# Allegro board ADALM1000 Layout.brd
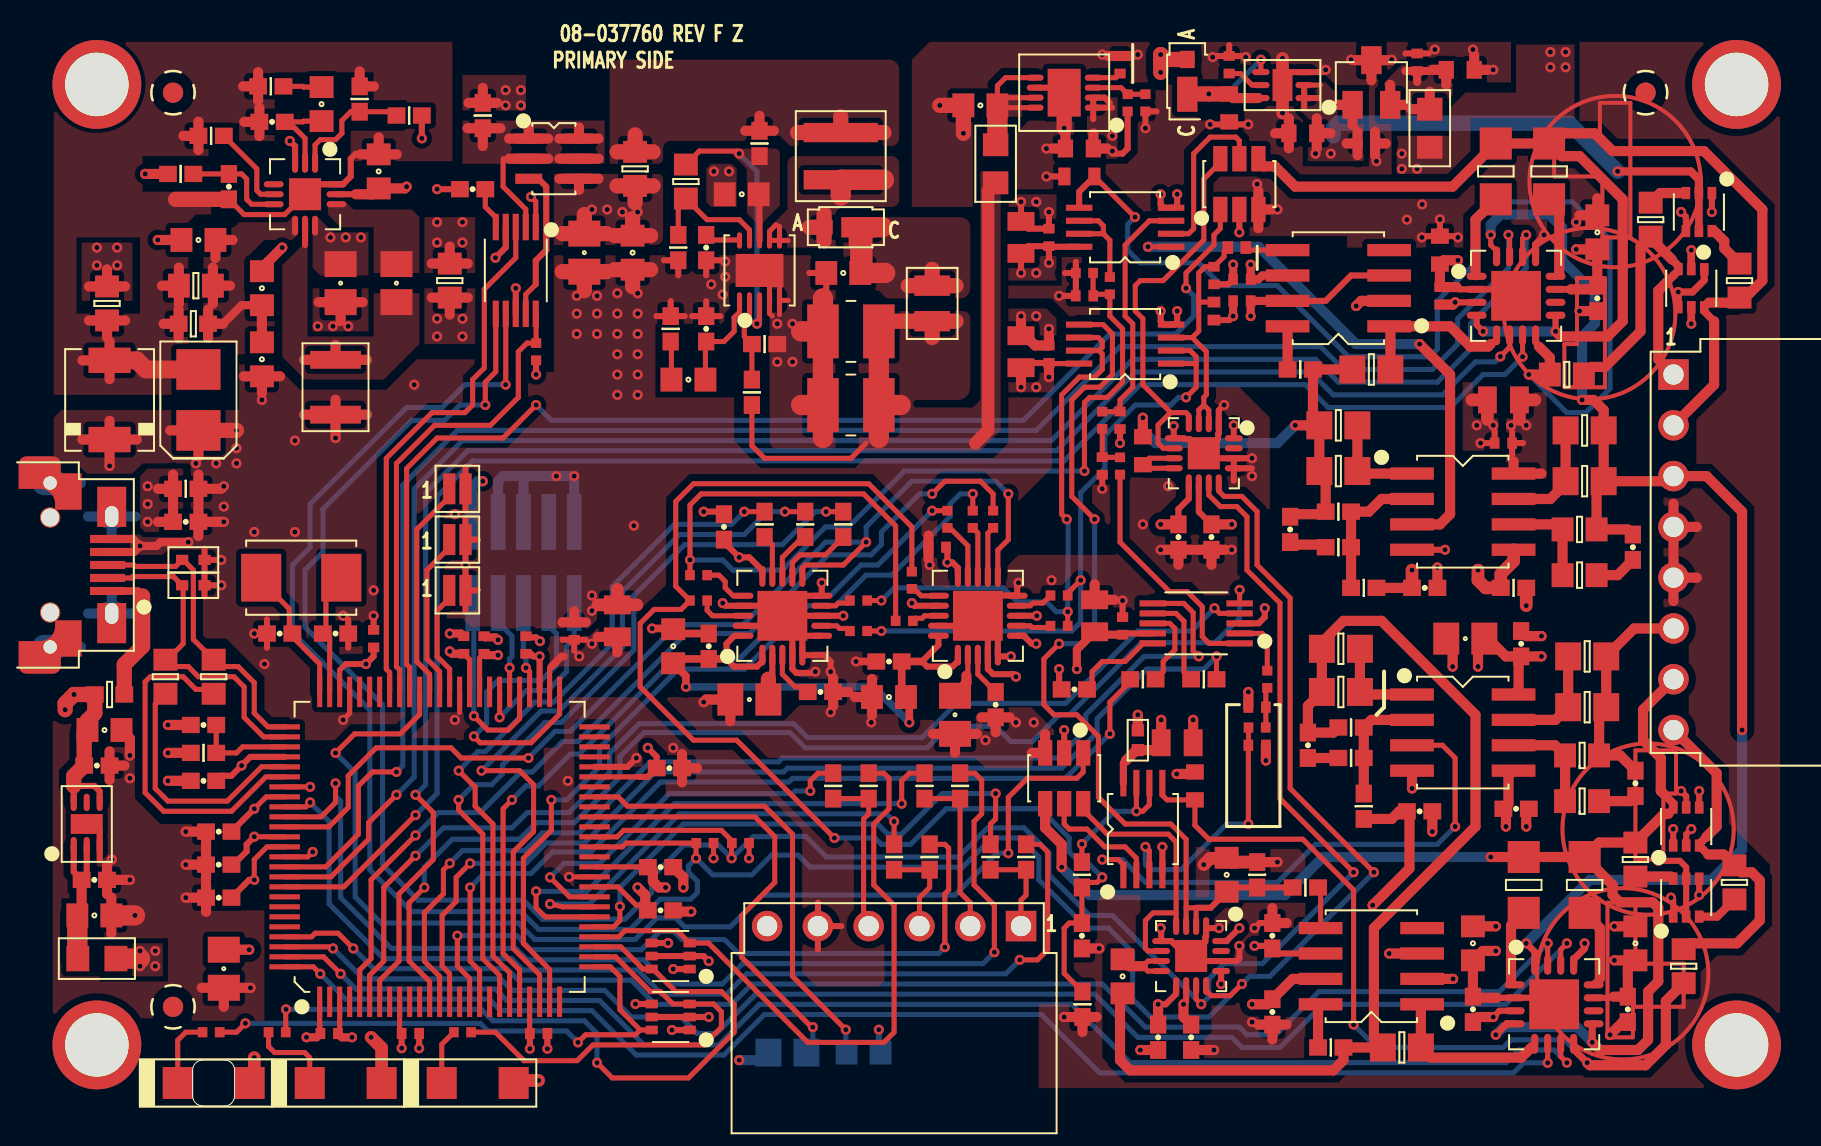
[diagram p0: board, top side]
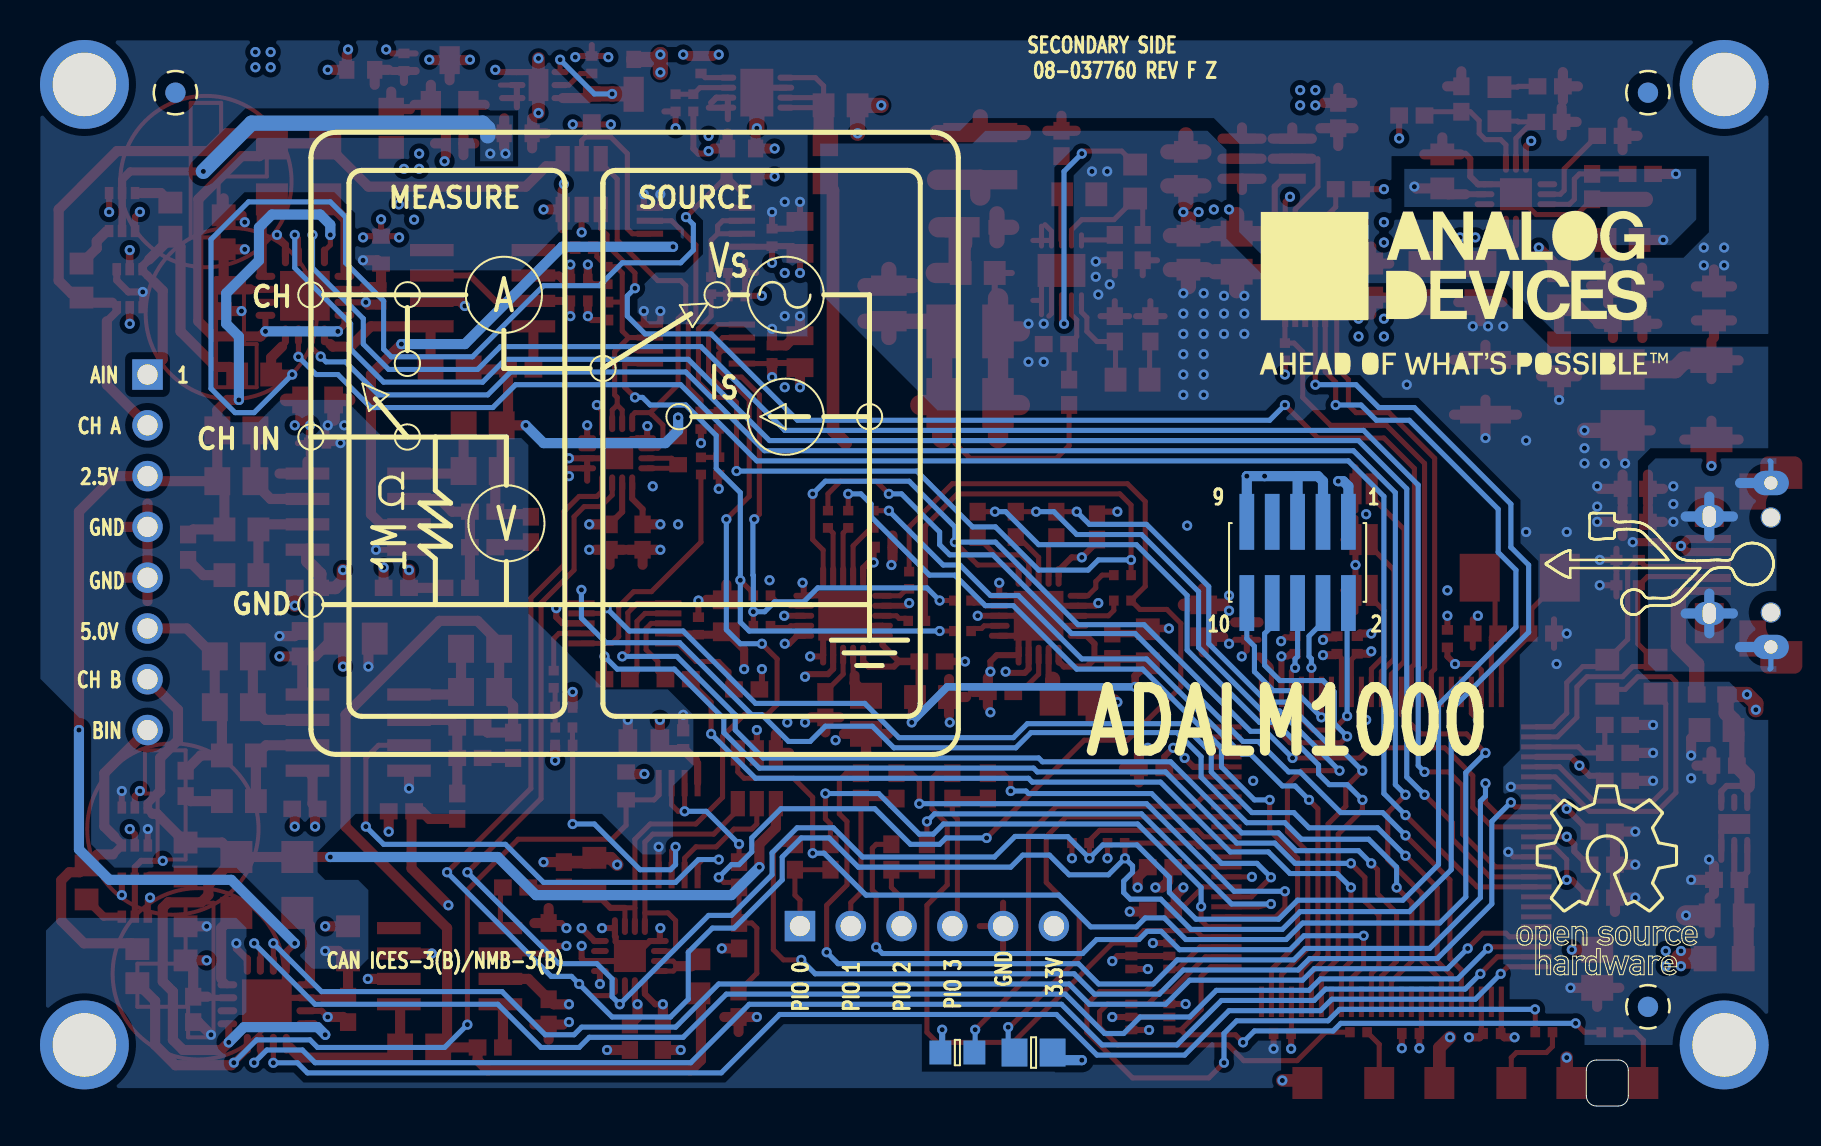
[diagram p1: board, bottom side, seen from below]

Outline 2.1 x 2.3 mm; copper layers: TOP, L2_GND, L3_VDD, BOTTOM. Coordinates in mm from the lower left corner of the outline.
Outline path: 0,1.79 0,0.51 arc(0.15,0.15) 0.51,0 1.59,0 arc(1.95,0.15) 2.1,0.51 2.1,1.79 arc(1.95,2.15) 1.59,2.3 0.51,2.3 arc(0.15,2.15) 0,1.79

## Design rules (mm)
constraint set DEFAULT: min track width 0.254
net group USB: nets D+ D-
net group USB_A: nets D+_A D-_A
nets with their own width: min track width 0.305; nets 1V8 2V5 3V3 5V0 6V0 -1V0 GND VCC

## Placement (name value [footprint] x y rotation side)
A2  ADG719BRTZ  [SOT23_6]  52.36 46.11 0 top
A3  ADA4661-2ARMZ  [MSOP8]  46.64 43.95 90 top
A4  AD8018ARZ  [SO8]  63.53 29.73 270 top
B2  ADG719BRTZ  [SOT23_6]  43.6 16.39 180 top
B3  ADA4661-2ARMZ  [MSOP8]  47.53 13.85 0 top
B4  AD8018ARZ  [SO8]  63.53 18.68 270 top
C1  10uF  [C0805]  1.56 6.87 270 top
C2  0.1UF  [C0402#2]  6.83 3.63 180 top
C3  10uF  [C0805#2]  21.24 24.26 90 top
C4  0.1UF  [C0402#2]  10.89 3.63 180 top
C5  10pF  [C0402]  0.54 19.06 0 top
C6  12PF  [C0402]  7.15 23.63 0 top
C7  12PF  [C0402]  4.35 23.63 180 top
C8  0.1UF  [C0402#2]  61.25 52.2 270 top
C9  0.1UF  [C0402]  -4.79 17.03 180 top
C10  1UF  [C0603#2]  63.41 51.82 0 top
C11  0.1UF  [C0402]  14 45.85 0 top
C12  4.7uF  [C0603]  -4.41 18.8 0 top
C13  0.1UF  [C0402#2]  58.71 48.14 180 top
C14  0.1UF  [C0402]  -4.92 11.31 180 top
C15  4.7uF  [C0603]  -4.92 9.53 0 top
C17  1UF  [C0603]  22.01 42.68 270 top
C18  10uF  [C0805]  19.59 42.68 90 top
C19  0.1UF  [C0402#2]  17.31 3.63 180 top
C20  10pF  [C0402]  25.69 38.87 90 top
C21  0.1UF  [C0402#2]  37.25 27.95 0 top
C22  1UF  [C0603]  34.83 20.45 180 top
C23  1UF  [C0603]  27.47 45.6 180 top
C24  0.1UF  [C0402]  23.4 9.79 180 top
C25  0.1UF  [C0402]  34.83 22.23 0 top
C26  0.01uF  [C0402]  44.48 8.52 90 top
C27  0.0056uF  [C0603#3]  51.09 41.54 270 top
C28  0.0056uF  [C0603]  51.72 11.56 90 top
C29  47uF  [C1210-2]  32.93 35.06 180 top
C30  1UF  [C0603]  32.55 41.66 180 top
C31  0.01uF  [C0402]  66.2 14.87 0 top
C32  0.1UF  [C0402]  23.4 11.95 180 top
C33  0.1UF  [C0402#2]  19.08 23.76 270 top
C34  0.1UF  [C0402]  23.85 16.9 180 top
C35  0.1UF  [C0402#2]  14.58 23.06 270 top
C36  0.1UF  [C0402#2]  16.67 23.06 270 top
C37  0.1UF  [C0402#2]  9.05 23.38 270 top
C38  0.1UF  [C0402]  26.58 28.96 270 top
C39  0.001uF  [C0603]  46.52 6.48 270 top
C40  0.1UF  [C0402]  61.38 14.74 180 top
C41  0.1UF  [C0402#2]  42.83 37.6 270 top
C42  0.01uF  [C0402#2]  44.61 40.52 0 top
C43  0.001uF  [C0603#2]  47.53 32.77 90 top
C44  0.1UF  [C0402]  61.63 25.92 180 top
C45  47uF  [C1210-2]  32.93 38.74 180 top
C46  0.1UF  [C0402]  70.27 40.39 90 top
C47  10uF  [C0805#2]  41.44 37.73 90 top
C48  0.1UF  [C0402#2]  13.56 23.06 270 top
C49  0.1UF  [C0402#2]  52.49 40.27 0 top
C50  0.1UF  [C0402]  1.3 13.72 0 top
C51  0.1UF  [C0402]  0.54 16.26 0 top
C52  0.1UF  [C0402]  1.3 12.07 0 top
C53  0.1UF  [C0402]  1.3 10.42 0 top
C54  0.1UF  [C0402#2]  42.83 43.44 270 top
C55  0.1UF  [C0402]  48.29 3.44 270 top
C56  0.1UF  [C0402]  49.95 3.44 90 top
C57  10pF  [C0402]  72.17 16.14 90 top
C58  0.1UF  [C0402]  71.79 4.83 90 top
C59  1UF  [C0603]  24.04 22.99 90 top
C61  0.1UF  [C0402]  25.82 22.99 270 top
C62  1UF  [C0603]  72.17 8.14 90 top
C63  0.1UF  [C0402#2]  46.52 24.01 270 top
C64  10uF  [C0805#2]  45.12 24.52 270 top
C65  0.1UF  [C0402]  49.31 28.46 270 top
C66  0.1UF  [C0402]  50.96 28.46 90 top
C67  33pF  [C0402]  54.9 28.84 90 top
C68  1UF  [C0603]  70.27 43.7 90 top
C69  0.1UF  [C0402#2]  52.49 41.35 180 top
C70  0.1UF  [C0402]  54.01 8.52 90 top
C71  0.1UF  [C0402]  54.01 4.71 90 top
C72  10uF  [C0805]  27.85 20.33 0 top
C73  10uF  [C0805]  38.13 19.57 90 top
C74  0.1UF  [C0402]  31.4 20.71 180 top
C75  0.1UF  [C0402]  40.17 20.07 90 top
C76  10uF  [C0805#2]  41.44 43.44 90 top
C77  0.1UF  [C0402#2]  65.57 33.15 0 top
C78  10uF  [C0805#2]  65.57 35.31 180 top
C79  0.1UF  [C0402#3]  47.28 18.3 270 top
C80  10uF  [C0805#2]  49.25 18.17 0 top
C81  0.1UF  [C0402]  66.46 23.12 270 top
C82  10uF  [C0805]  63.66 23.38 180 top
C84  33pF  [C0402]  55.79 18.04 90 top
C90  0.1UF  [C0402#2]  62.39 40.52 90 top
C91  1UF  [C0603#2]  62.39 42.81 90 top
C92  0.1UF  [C0402]  64.04 4.83 90 top
C93  1UF  [C0603]  64.04 8.14 90 top
C94  0.01uF  [C0402#2]  45.5 32.01 90 top
C95  0.01uF  [C0402#2]  53.25 19.95 0 top
C96  1000PF  [C0402#2]  46.39 34.3 270 top
C97  1000PF  [C0402#2]  53.25 18.04 0 top
C99  0.1UF  [C0402]  44.1 20.84 0 top
C101  10pF  [C0402]  -0.35 29.22 180 top
C102  10pF  [C0402]  72.04 27.95 90 top
C104  4.7uF  [C0603]  39.4 50.05 180 top
C105  0.01uF  [C0402#2]  46.39 52.08 270 top
C106  4.7uF  [C0603#2]  44.36 47.89 180 top
C107  2.2uF  [C0603#2]  51.85 49.92 270 top
C108  2.2uF  [C0603#2]  55.53 48.65 180 top
C109  0.01uF  [C0402]  25.69 42.93 90 top
C110  0.082UF  [C0603]  24.8 36.33 0 top
C112  0.01uF  [C0402#2]  51.85 52.08 270 top
CBST  0.01uF  [C0805]  10.19 41.16 270 top
CC  1UF  [C0603]  3.46 40.9 90 top
CC1  2700PF  [C0603]  6.45 50.11 270 top
CC2  22PF  [C0402]  3.97 49.22 0 top
CIN1  10uF  [C0805]  7.4 41.16 270 top
COUT1  4.7uF  [C0603]  3.46 37.35 90 top
COUT2  47UF  [C3528]  0.29 35.31 90 top
CSS  TBD0402  [C0402]  1.81 45.98 90 top
CVCC  1UF  [C0603]  9.31 46.74 90 top
CVCC2  1UF  [C0603]  0.29 43.31 0 top
D1  B160B-13-F  [DIO214AA]  -4.16 35.31 90 top
D2  BAT54SDW-7-F  [SOT363H43]  75.35 44.71 180 top
D3  PD3S130L-7  [POWERDI323]  49.75 51.25 90 top
D4  PD3S130L-7  [POWERDI323]  32.67 43.95 180 top
D5  BAT54SDW-7-F  [SOT363H43]  23.91 4.45 90 top
D6  BAT54SDW-7-F  [SOT363H43]  23.91 7.5 90 top
D7  BAT54SDW-7-F  [SOT363H43]  74.96 40.9 180 top
D8  MLESD12A-0402-TP  [D0402]  0.03 26.04 180 top
D9  MLESD12A-0402-TP  [D0402]  0.03 27.31 180 top
D10  BAT54SDW-7-F  [SOT363H43]  74.71 13.98 0 top
D11  BAT54SDW-7-F  [SOT363H43]  74.71 10.42 0 top
DS1  LTST-C230KRKT  [LED1206H11]  1.05 1.15 0 top
DS2  LTST-C230KGKT  [LED1206H11]  7.65 1.15 0 top
DS3  LTST-C230TBKT  [LED1206H11]  14.26 1.15 0 top
E1  330OHM  [L0603]  -4.16 20.58 0 top
E2  100OHM  [L0805]  61.88 48.9 270 top
E3  100OHM  [L0805]  -4.79 7.37 0 top
E4  100OHM  [L0805]  40.17 47.12 90 top
JTAG  FTSH-105-01-L-DV-TR  [CNHDR2X5H245]  16.54 27.19 0 bottom
L1  2.2uH  [LSML126W90H59]  7.15 35.95 270 top
L2  1uH  [L0603]  0.03 39.12 0 top
L3  4.7uH  [LSMSQ157H122]  32.42 47.51 270 top
L4  110nH  [L9075]  36.99 40.14 270 top
NOREF  -  []  -6.12 35.06 0 top
NOREF#2  -  [unnamed#2]  -0.98 4.96 0 top
NOREF#3  -  []  14.19 0.26 0 top
NOREF#4  -  []  1.1 0.35 0 top
NOREF#5  -  []  7.72 0.35 0 top
NOREF#6  -  [unnamed#2]  77.23 3.06 0 top
NOREF#7  -  []  -148.3 -209.03 0 top
NOREF#8  -  []  -148.3 -209.03 0 top
NOREF#9  -  []  -8.78 29.78 0 top
NOREF#10  -  []  -101.54 140.49 0 top
NOREF#11  -  []  -6.57 24.52 0 top
NOREF#12  -  [unnamed#2]  -0.98 50.68 0 top
NOREF#13  -  []  111.16 107.32 0 top
NOREF#14  -  []  -142.97 -60.74 0 top
NOREF#15  -  []  166.02 61.48 0 top
NOREF#16  -  [unnamed#2]  -7.13 29.43 0 top
NOREF#17  -  [unnamed#2]  77.23 51.09 0 top
NOREF#18  -  [unnamed#2]  -4.79 3.06 0 top
NOREF#19  -  []  37.76 69.2 0 top
NOREF#20  -  []  -148.3 -209.03 0 top
NOREF#21  -  [unnamed#2]  -7.13 24.68 0 top
NOREF#22  -  []  14.8 0.51 0 top
NOREF#23  -  [unnamed#2]  72.68 50.68 0 top
NOREF#24  -  [unnamed#2]  -4.79 51.09 0 top
NOREF#25  -  []  8.8 40.65 180 bottom
NOREF#26  -  [unnamed#2]  -0.98 50.68 180 bottom
NOREF#27  -  [unnamed#2]  72.68 50.68 180 bottom
NOREF#28  -  [unnamed#2]  -0.98 4.96 180 bottom
P1  10103592-0001LF  [CNFCI10103592-0001LF]  -6.96 27.06 90 top
P2  PPPC081LGBN-RC  [CNHDRRA1X8H108]  74.08 36.58 270 top
P3  PPPC061LGBN-RC  [CNHDRRA1X6H108]  41.44 9 180 top
P4  -  [JPSLD02]  13.24 25.79 0 top
P5  -  [JPSLD02]  13.24 28.33 0 top
P6  -  [JPSLD02]  13.24 30.87 0 top
Q1  SI3456DDV-T1-GE3  [TSOP6]  18.07 47.38 270 top
R1  10K  [R0402]  25.62 13.15 180 top
R2  10K  [R0402]  27.4 13.15 180 top
R3  6.8K  [R0402#2]  0.54 17.66 0 top
R4  39  [R0603]  1.05 21.47 90 top
R5  39  [R0603]  -1.36 21.47 90 top
R6  0.1  [R0402#2]  14.51 49.54 270 top
R7  150  [R0402#2]  44.48 11.56 90 top
R8  1MEG  [R0603#2]  50.14 16.01 90 top
R9  10K  [R0402#2]  58.58 14.99 90 top
R10  10K  [R0402#2]  57.95 18.93 180 top
R11  0  [R0603]  24.67 46.24 90 top
R12  62K  [R0402#2]  24.29 42.93 270 top
R13  0  [R0805]  29.75 2.67 0 bottom
R14  4.7K  [R0402#2]  39.91 12.45 270 top
R15  255  [R0402#3]  52.23 42.93 180 top
R16  255  [R0402#2]  55.66 10.93 180 top
R17  1K  [R0402#2]  66.07 25.92 0 top
R18  53.6K  [R0402#2]  27.97 35.69 90 top
R19  12.7K  [R0402#2]  28.61 38.11 180 top
R20  150  [R0402]  45.88 41.03 90 top
R21  0  [R0402#2]  -0.6 46.62 180 top
R22  1.02K  [R0402#3]  51.09 39.76 270 top
R23  4.7K  [R0402#2]  36.61 16.01 270 top
R24  10K  [R0402#2]  58.58 25.92 180 top
R25  10K  [R0402#2]  57.31 29.73 180 top
R26  100  [R0402#2]  57.31 27.95 180 top
R27  604  [R0402#2]  44.51 5.09 270 top
R28  49.9  [R1206]  67.85 46.74 90 top
R29  100  [R0603]  68.74 36.58 0 top
R30  0.5  [R0805]  58.96 36.84 0 top
R31  100  [R0603]  74.58 6.99 90 top
R32  0.5  [R0805]  60.49 2.93 0 top
R33  2.49K  [R0603]  69.5 17.53 0 top
R34  100  [R0402#2]  57.95 17.41 180 top
R35  4.7K  [R0402#2]  35.09 12.45 270 top
R36  0  [R0603]  -4.28 40.14 270 top
R37  0  [R0603]  12.86 41.28 270 top
R38  1MEG  [R0603#3]  44.36 46.49 180 top
R39  2.49K  [R0603]  69.38 28.84 0 top
R40  1.02K  [R0402#2]  53.25 11.56 90 top
R41  130  [R0402]  0.92 3.69 0 top
R42  130  [R0402]  13.5 3.69 0 top
R43  130  [R0402]  4.23 3.69 0 top
R44  4.7K  [R0402#2]  32.04 16.01 270 top
R45  1  [R0402#2]  28.36 48.14 90 top
R46  8.06  [R0805]  57.31 31.76 180 top
R47  8.06  [R0805]  57.31 34.04 180 top
R48  49.9  [R1206]  65.19 46.74 90 top
R49  8.06  [R0805]  69.63 33.79 0 top
R50  220  [R0402#2]  41.69 12.45 90 top
R51  220  [R0402#2]  36.86 12.45 90 top
R52  220  [R0402#2]  38.39 16.01 90 top
R53  220  [R0402#2]  33.82 16.01 90 top
R54  0  [R0603]  22.13 46.87 90 top
R55  100K  [R0402#2]  -0.35 30.87 180 top
R56  0  [R0603]  33.56 2.67 180 bottom
R57  8.06  [R0805]  69.63 31.25 0 top
R58  100  [R0603]  69.5 15.25 0 top
R59  8.06  [R0805]  57.44 22.87 180 top
R60  100  [R0603]  69.38 26.55 0 top
R61  8.06  [R0805]  57.44 20.71 180 top
R62  604  [R0402]  44.61 41.66 180 top
R63  49.9  [R1206]  69.63 11.06 90 top
R64  49.9  [R1206]  66.58 11.06 90 top
R65  8.06  [R0805]  69.76 19.95 0 top
R66  8.06  [R0805]  69.76 22.49 0 top
R67  10  [R0603]  72.17 12.33 270 top
R68  10  [R0603]  77.12 11.18 270 top
R69  10  [R0402]  25.31 26.55 0 top
R70  10  [R0603]  77.38 41.28 90 top
R71  10  [R0603]  72.93 44.33 90 top
R72  33  [R0402#2]  50.58 21.34 180 top
R73  33  [R0402#2]  47.53 21.34 0 top
R74  150  [R0402]  46.39 32.01 90 top
R75  150  [R0402]  53.76 21.34 270 top
R76  1.5K  [R0402]  45.5 34.3 90 top
R77  1.5K  [R0402]  53.25 18.93 180 top
R78  33  [R0402#2]  32.55 29.09 270 top
R79  33  [R0402#2]  30.64 29.09 270 top
R80  33  [R0402#2]  28.61 29.09 90 top
R81  33  [R0402]  40.04 29.34 270 top
R82  33  [R0402]  39.02 29.34 270 top
R83  33  [R0402]  37.75 29.34 90 top
R84  0.5  [R0402#2]  55.41 36.84 180 top
R85  0.5  [R0402#2]  56.93 2.93 180 top
R86  10  [R0402]  33.31 23.76 180 top
R87  10  [R0402]  35.98 26.3 270 top
R88  10  [R0402]  43.34 24.01 180 top
R89  10  [R0402]  25.31 25.28 0 top
R90  10  [R0402]  33.31 25.28 180 top
R91  10  [R0402]  35.59 24.26 0 top
R92  10  [R0402]  43.34 25.53 180 top
R93  10K  [R0402]  17.18 37.73 90 top
R95  10.5K  [R0402#2]  23.91 38.87 270 top
R97  20K  [R0402]  46.77 50.17 90 top
R98  4.99K  [R0402]  47.66 50.17 270 top
RC1  11.3K  [R0402#2]  3.91 51 0 top
RF1  23.2K  [R0402#2]  10.83 49.54 0 top
RF2  34.8K  [R0402#2]  8.35 50.36 270 top
RFILT  1  [R0603]  0.16 41.03 0 top
RFREQ  88.7K  [R0402#2]  0.92 48.52 0 top
U1  ATSAM3U2CA-AU  [LQFP100]  12.35 12.96 0 top
U2  ADM1178-1ARMZ  [RM10]  16.16 41.79 180 top
U3  ADP7118ACPZN3.3  [DFN6_2X2_PAD1_6X1]  -5.3 14.1 0 top
U4  ADR381ARTZ  [SOT23]  58.96 51.19 0 top
U5  ADP2442ACPZ  [QFN12_3X3_PAD1_6X1_6]  5.62 45.6 180 top
U6  ADM7171ACPZ  [DFN8_3X3_PAD2_38X1_64]  43.6 50.68 90 top
U7  ADP7118ACPZN5.0  [DFN6_2X2_PAD1_6X1]  54.52 51.06 90 top
U8  ADA4661-2ARMZ  [MSOP8]  46.64 38.11 90 top
U9  ADP1614ACPZ-1.3  [QFN10_3X3_PAD2_38X1_64]  28.36 41.79 0 top
U10  AD5663RBRMZ-5  [RM10]  50.2 24.14 90 top
U11  AD7682BCPZ  [QFN20_4X4_PAD2_5X2_5]  29.5 24.52 0 top
U12  AD7682BCPZ  [QFN20_4X4_PAD2_5X2_5]  39.28 24.52 0 top
UA9  AD5122ABCPZ10  [QFN16_3X3_PAD1_6X1_6]  50.58 32.65 180 top
UA11  ADG1611BCPZ  [QFN16_4X4_PAD2_5X2_5]  66.2 40.52 270 top
UA12  AD8210WYRZ  [SO8]  57.31 40.9 90 top
UB9  AD5122ABCPZ10  [QFN16_3X3_PAD1_6X1_6]  49.95 7.5 180 top
UB11  ADG1611BCPZ  [QFN16_4X4_PAD2_5X2_5]  68.11 5.09 270 top
UB12  AD8210WYRZ  [SO8]  58.96 6.99 90 top
Y1  12MEGHZ  [YSML197W126H59]  5.43 26.42 180 top

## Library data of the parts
A2 B2 = ADG719BRT: User Part Number: UPN; Tolerance: N/A; alternate symbols: (); part number: ADG719BRT_SM-ADG719BRTZ,E005069,SOT23_6; tolerance: N/A
A3 B3 U8 = ADA4661_2_V2: Tolerance: N/A; User Part Number: UPN; alternate symbols: (); part number: ADA4661_2_V2_SM-ADA4661-2ARMZ,E019683,MSOP8; tolerance: N/A
A4 B4 = AD8018: Tolerance: N/A; User Part Number: UPN; alternate symbols: (); part number: AD8018_SM-AD8018ARZ,E020278,SO8; tolerance: N/A
C1 C18 C72 C73 C82 CIN1 = CAP: Tolerance: 10; User Part Number: UPN; alternate symbols: (); part number: CAP_SM-10UF,25V,10,E019080,C0805; tolerance: 10
C2 C4 C8 C13 C19 C21 C33 C35-C37 C41 C48 C49 C54 C61 C63 C69 C77 C90 C99 = CAP: Tolerance: 10; User Part Number: UPN; alternate symbols: C0402L_ALT; part number: CAP_SM-0.1UF,16V,10,E027519,C0402; tolerance: 10
C3 C47 C64 C76 C78 C80 = CAP: User Part Number: UPN; Tolerance: 10; alternate symbols: C0805L; part number: CAP_SM-10UF,25V,10,E019080,C0805; tolerance: 10
C5 C20 C57 C101 C102 = CAP: Tolerance: 5; User Part Number: UPN; alternate symbols: (); part number: CAP_SM-10PF,50V,5,E007982,C0402; tolerance: 5
C6 C7 = CAP: Tolerance: 5; User Part Number: UPN; alternate symbols: (); part number: CAP_SM-12PF,50V,5,E033360,C0402; tolerance: 5
C9 C11 C14 C24 C25 C32 C34 C38 C40 C44 C46 C50-C53 C55 C56 C58 C65 C66 C70 C71 C74 C75 C81 C92 = CAP: Tolerance: 10; User Part Number: UPN; alternate symbols: (); part number: CAP_SM-0.1UF,16V,10,E027519,C0402; tolerance: 10
C10 C59 C91 = CAP: Tolerance: 10; User Part Number: UPN; alternate symbols: C0603L_ALT; part number: CAP_SM-1UF,25V,10,E026591,C0603; tolerance: 10
C12 C15 COUT1 = CAP: Tolerance: 10; User Part Number: UPN; alternate symbols: (); part number: CAP_SM-4.7UF,6.3V,10,E010382,C0603; tolerance: 10
C17 C22 C23 C30 C62 C68 C93 CC CVCC CVCC2 = CAP: Tolerance: 10; User Part Number: UPN; alternate symbols: (); part number: CAP_SM-1UF,25V,10,E026591,C0603; tolerance: 10
C26 = CAP: Tolerance: 10; User Part Number: UPN; alternate symbols: (); part number: CAP_SM-0.01UF,50V,10,E019413,C0402; tolerance: 10
C27 = CAP: Tolerance: 5; User Part Number: UPN; alternate symbols: C0402L_ALT; part number: CAP_SM-0.0056UF,50V,5,E012693,C0603; tolerance: 5
C28 = CAP: Tolerance: 5; User Part Number: UPN; alternate symbols: (); part number: CAP_SM-0.0056UF,50V,5,E012693,C0603; tolerance: 5
C29 C45 = CAP: Tolerance: 10; User Part Number: UPN; alternate symbols: (); part number: CAP_SM-47UF,10V,10,E011546,C1210-2; tolerance: 10
C31 C109 = CAP: Tolerance: 10; User Part Number: UPN; alternate symbols: (); part number: CAP_SM-0.01UF,25V,10,E019646,C0402; tolerance: 10
C39 = CAP: Tolerance: 5; User Part Number: UPN; alternate symbols: (); part number: CAP_SM-0.001UF,50V,5,E007908,C0603; tolerance: 5
C42 C94 C95 = CAP: Tolerance: 10; User Part Number: UPN; alternate symbols: C0402L_ALT; part number: CAP_SM-0.01UF,50V,10,E019413,C0402; tolerance: 10
C43 = CAP: Tolerance: 5; User Part Number: UPN; alternate symbols: C0603L_ALT; part number: CAP_SM-0.001UF,50V,5,E007908,C0603; tolerance: 5
C67 C84 = CAP: Tolerance: 5; User Part Number: UPN; alternate symbols: (); part number: CAP_SM-33PF,50V,5,E007907,C0402; tolerance: 5
C79 = CAP: Tolerance: 10; User Part Number: UPN; alternate symbols: C0402_ALT; part number: CAP_SM-0.1UF,16V,10,E027519,C0402; tolerance: 10
C96 C97 = CAP: Tolerance: 10; User Part Number: UPN; alternate symbols: C0402L_ALT; part number: CAP_SM-1000PF,25V,10,E025706,C0402; tolerance: 10
C104 C106 = CAP: Tolerance: 10; User Part Number: UPN; alternate symbols: C0603L_ALT; part number: CAP_SM-4.7UF,16V,10,E020112,C0603; tolerance: 10
C105 C112 = CAP: Tolerance: 10; User Part Number: UPN; alternate symbols: C0402L_ALT; part number: CAP_SM-0.01UF,25V,10,E019646,C0402; tolerance: 10
C107 C108 = CAP: Tolerance: 10; User Part Number: UPN; alternate symbols: C0603L_ALT; part number: CAP_SM-2.2UF,10V,10,E015288,C0603; tolerance: 10
C110 = CAP: Tolerance: 10; User Part Number: UPN; alternate symbols: (); part number: CAP_SM-0.082UF,16V,10,E000419,C0603; tolerance: 10
CBST = CAP: Tolerance: 5; User Part Number: UPN; alternate symbols: (); part number: CAP_SM-0.01UF,50V,5,E012401,C0805; tolerance: 5
CC1 = CAP: Tolerance: 5; User Part Number: UPN; alternate symbols: (); part number: CAP_SM-2700PF,50V,5,E026401,C0603; tolerance: 5
CC2 = CAP: Tolerance: 5; User Part Number: UPN; alternate symbols: (); part number: CAP_SM-22PF,50V,5,E000265,C0402; tolerance: 5
COUT2 = CAPP: User Part Number: UPN; Tolerance: 10; alternate symbols: (); part number: CAPP_SM-47UF,10V,10,E014885,C3528; tolerance: 10
CSS = CAP: User Part Number: UPN; alternate symbols: (); part number: CAP_SM-TBD0402,TBD0402,TBD0402,E000381,C0402
D1 = DIOSCHOTTKY: User Part Number: UPN; Tolerance: N/A; alternate symbols: (); part number: DIOSCHOTTKY_SM-B160B-13-F,60V,N/A,E006709,DIO214AA; tolerance: N/A
D2 D5-D7 D10 D11 = DIO6P_V2: User Part Number: UPN; Tolerance: N/A; alternate symbols: (); part number: DIO6P_V2_SM-BAT54SDW-7-F,30V,N/A,E016644,SOT363H43; tolerance: N/A
D3 D4 = DIOSCHOTTKY: Tolerance: N/A; User Part Number: UPN; alternate symbols: (); part number: DIOSCHOTTKY_SM-PD3S130L-7,30V,N/A,E021289,POWERDI323; tolerance: N/A
D8 D9 = DIOZNR_V2: Tolerance: N/A; User Part Number: UPN; alternate symbols: (); part number: DIOZNR_V2_SM-MLESD12A-0402-TP,12V,N/A,E023287,D0402; tolerance: N/A
DS1 = DIOLED: User Part Number: UPN; Tolerance: N/A; alternate symbols: (); part number: DIOLED_SM-LTST-C230KRKT,2V,N/A,E027097,LED1206H11; tolerance: N/A
DS2 = DIOLED: User Part Number: UPN; Tolerance: N/A; alternate symbols: (); part number: DIOLED_SM-LTST-C230KGKT,2V,N/A,E027102,LED1206H11; tolerance: N/A
DS3 = DIOLED: User Part Number: UPN; Tolerance: N/A; alternate symbols: (); part number: DIOLED_SM-LTST-C230TBKT,3.3V,N/A,E027101,LED1206H11; tolerance: N/A
E1 = FERRITE: Tolerance: 25; User Part Number: UPN; alternate symbols: (); part number: FERRITE_SM-330OHM,25,E015984,L0603; tolerance: 25
E2-E4 = FERRITE: Tolerance: 25; User Part Number: UPN; alternate symbols: (); part number: FERRITE_SM-100OHM,25,E012241,L0805; tolerance: 25
JTAG = CN10P_ODD_EVEN: Tolerance: N/A; User Part Number: UPN; alternate symbols: (); part number: CN10P_ODD_EVEN_SM-FTSH-105-01-L-DV-TR,E019864,CNHDR2X5H245; tolerance: N/A
L1 = IND: User Part Number: UPN; Tolerance: 20; alternate symbols: (); part number: IND_SM-2.2UH,20,E018625,LSML126W90H59; tolerance: 20
L2 = IND: Tolerance: 20; User Part Number: UPN; alternate symbols: (); part number: IND_SM-1UH,20,E015929,L0603; tolerance: 20
L3 = IND: User Part Number: UPN; Tolerance: 20; alternate symbols: (); part number: IND_SM-4.7UH,20,E013623,LSMSQ157H122; tolerance: 20
L4 = IND: Tolerance: 5; User Part Number: UPN; alternate symbols: (); part number: IND_SM-110NH,5,E016398,L9075; tolerance: 5
P1 = CN5P_4PSHLD: User Part Number: UPN; Tolerance: N/A; alternate symbols: (); part number: CN5P_4PSHLD_SM-10103592-0001LF,E021325,CNFCI10103592-0001LF; tolerance: N/A
P2 = CN8P_A: User Part Number: UPN; Tolerance: N/A; alternate symbols: (); part number: CN8P_A_TH-PPPC081LGBN-RC,E023551,CNHDRRA1X8H108; tolerance: N/A
P3 = CN6P: User Part Number: UPN; Tolerance: N/A; alternate symbols: (); part number: CN6P_TH-PPPC061LGBN-RC,E020346,CNHDRRA1X6H108; tolerance: N/A
P4-P6 = NC2P: User Part Number: UPN; Tolerance: N/A; alternate symbols: (); part number: NC2P_SM-JPSLD02,E006230,JPSLD02; tolerance: N/A
Q1 = TRANSI3460: Tolerance: N/A; User Part Number: UPN; alternate symbols: (); part number: TRANSI3460_SM-SI3456DDV-T1-GE3,E016316,TSOP6; tolerance: N/A
R1 R2 R93 = RES: Tolerance: 1; User Part Number: UPN; alternate symbols: R0402L_ALT; part number: RES_SM-10K,E003751,1/10W,1,R0402; tolerance: 1
R3 = RES: Tolerance: 1; User Part Number: UPN; alternate symbols: (); part number: RES_SM-6.8K,E011558,1/10W,1,R0402; tolerance: 1
R4 R5 = RES: Tolerance: 1; User Part Number: UPN; alternate symbols: (); part number: RES_SM-39,E004235,1/16W,1,R0603; tolerance: 1
R6 = RES: Tolerance: 1; User Part Number: UPN; alternate symbols: (); part number: RES_SM-0.1,E017078,1/6W,1,R0402; tolerance: 1
R7 = RES: Tolerance: 1; User Part Number: UPN; alternate symbols: (); part number: RES_SM-150,E017444,1/10W,1,R0402; tolerance: 1
R8 = RES: Tolerance: 1; User Part Number: UPN; alternate symbols: C0603L_ALT; part number: RES_SM-1MEG,E003682,1/10W,1,R0603; tolerance: 1
R9 R10 R24 R25 = RES: Tolerance: 1; User Part Number: UPN; alternate symbols: (R0402L); part number: RES_SM-10K,E003751,1/10W,1,R0402; tolerance: 1
R11 R36 R37 R54 R56 = RES: Tolerance: N/A; User Part Number: UPN; alternate symbols: (); part number: RES_SM-0,E007502,N/A,N/A,R0603; tolerance: N/A
R12 = RES: Tolerance: 1; User Part Number: UPN; alternate symbols: (); part number: RES_SM-62K,E021391,1/16W,1,R0402; tolerance: 1
R13 = RES: Tolerance: N/A; User Part Number: UPN; alternate symbols: (); part number: RES_SM-0,E004152,1/10W,N/A,R0805; tolerance: N/A
R14 R23 R35 R44 = RES: Tolerance: 1; User Part Number: UPN; alternate symbols: (R0402L); part number: RES_SM-4.7K,E008190,1/10W,1,R0402; tolerance: 1
R15 = RES: User Part Number: UPN; Tolerance: 1; alternate symbols: (R0402L); part number: RES_SM-255,E027098,1/10W,1,R0402; tolerance: 1
R16 = RES: Tolerance: 1; User Part Number: UPN; alternate symbols: (R0402L); part number: RES_SM-255,E027098,1/10W,1,R0402; tolerance: 1
R17 = RES: Tolerance: 1; User Part Number: UPN; alternate symbols: (); part number: RES_SM-1K,E003763,1/10W,1,R0402; tolerance: 1
R18 = RES: Tolerance: 1; User Part Number: UPN; alternate symbols: (); part number: RES_SM-53.6K,E023305,1/16W,1,R0402; tolerance: 1
R19 = RES: Tolerance: 1; User Part Number: UPN; alternate symbols: (); part number: RES_SM-12.7K,E019976,1/10W,1,R0402; tolerance: 1
R20 R74 R75 = RES: Tolerance: 1; User Part Number: UPN; alternate symbols: R0402L_ALT; part number: RES_SM-150,E017444,1/10W,1,R0402; tolerance: 1
R21 = RES: Tolerance: 1; User Part Number: UPN; alternate symbols: (); part number: RES_SM-0,E010661,1/16W,1,R0402; tolerance: 1
R22 = RES: User Part Number: UPN; Tolerance: 1; alternate symbols: (R0402L,R0402L_ALT); part number: RES_SM-1.02K,E027103,1/10W,1,R0402; tolerance: 1
R26 R34 = RES: Tolerance: 1; User Part Number: UPN; alternate symbols: (); part number: RES_SM-100,E003760,1/16W,1,R0402; tolerance: 1
R27 = RES: Tolerance: 1; User Part Number: UPN; alternate symbols: (); part number: RES_SM-604,E020998,1/10W,1,R0402; tolerance: 1
R28 R48 R63 R64 = RES: Tolerance: 1; User Part Number: UPN; alternate symbols: (); part number: RES_SM-49.9,E003114,1/4W,1,R1206; tolerance: 1
R29 R31 R58 R60 = RES: Tolerance: 1; User Part Number: UPN; alternate symbols: (); part number: RES_SM-100,E007883,1/16W,1,R0603; tolerance: 1
R30 R32 = RES: Tolerance: 1; User Part Number: UPN; alternate symbols: (); part number: RES_SM-0.5,E017079,1/3W,1,R0805; tolerance: 1
R33 R39 = RES: Tolerance: 1; User Part Number: UPN; alternate symbols: (); part number: RES_SM-2.49K,E006438,1/10W,1,R0603; tolerance: 1
R38 = RES: User Part Number: UPN; Tolerance: 1; alternate symbols: R0603L; part number: RES_SM-1MEG,E003682,1/10W,1,R0603; tolerance: 1
R40 = RES: Tolerance: 1; User Part Number: UPN; alternate symbols: (R0402L,R0402L_ALT); part number: RES_SM-1.02K,E027103,1/10W,1,R0402; tolerance: 1
R41-R43 = RES: Tolerance: 1; User Part Number: UPN; alternate symbols: R0402L_ALT; part number: RES_SM-130,E003795,1/16W,1,R0402; tolerance: 1
R45 = RES: Tolerance: 5; User Part Number: UPN; alternate symbols: (); part number: RES_SM-1,E019639,1/16W,5,R0402; tolerance: 5
R46 R47 R49 R57 R59 R61 R65 R66 = RES: Tolerance: 1; User Part Number: UPN; alternate symbols: (); part number: RES_SM-8.06,E003992,1/8W,1,R0805; tolerance: 1
R50-R53 = RES: Tolerance: 1; User Part Number: UPN; alternate symbols: (); part number: RES_SM-220,E011432,1/16W,1,R0402; tolerance: 1
R55 = RES: Tolerance: 5; User Part Number: UPN; alternate symbols: (); part number: RES_SM-100K,E003464,1/10W,5,R0402; tolerance: 5
R62 = RES: Tolerance: 1; User Part Number: UPN; alternate symbols: R0402L_ALT; part number: RES_SM-604,E020998,1/10W,1,R0402; tolerance: 1
R67 R68 R70 R71 = RES: Tolerance: 1; User Part Number: UPN; alternate symbols: (); part number: RES_SM-10,E003666,1/10W,1,R0603; tolerance: 1
R69 R86-R92 = RES: Tolerance: 1; User Part Number: UPN; alternate symbols: R0402L_ALT; part number: RES_SM-10,E017858,1/16W,1,R0402; tolerance: 1
R72 R73 R78-R80 = RES: Tolerance: 1; User Part Number: UPN; alternate symbols: (); part number: RES_SM-33,E020519,1/10W,1,R0402; tolerance: 1
R76 R77 = RES: Tolerance: 5; User Part Number: UPN; alternate symbols: R0402L_ALT; part number: RES_SM-1.5K,E025327,1/10W,5,R0402; tolerance: 5
R81-R83 = RES: Tolerance: 1; User Part Number: UPN; alternate symbols: R0402L_ALT; part number: RES_SM-33,E020519,1/10W,1,R0402; tolerance: 1
R84 R85 = RES: Tolerance: 1; User Part Number: UPN; alternate symbols: (); part number: RES_SM-0.5,E023524,1/16W,1,R0402; tolerance: 1
R95 = RES: Tolerance: 1; User Part Number: UPN; alternate symbols: (); part number: RES_SM-10.5K,E007860,1/16W,1,R0402; tolerance: 1
R97 = RES: Tolerance: 1; User Part Number: UPN; alternate symbols: R0402L_ALT; part number: RES_SM-20K,E003791,1/16W,1,R0402; tolerance: 1
R98 = RES: Tolerance: 1; User Part Number: UPN; alternate symbols: R0402L_ALT; part number: RES_SM-4.99K,E006643,1/16W,1,R0402; tolerance: 1
RC1 = RES: Tolerance: 0.1; User Part Number: UPN; alternate symbols: (); part number: RES_SM-11.3K,E019952,1/16W,0.1,R0402; tolerance: 0.1
RF1 = RES: Tolerance: 1; User Part Number: UPN; alternate symbols: (); part number: RES_SM-23.2K,E019517,1/16W,1,R0402; tolerance: 1
RF2 = RES: Tolerance: 1; User Part Number: UPN; alternate symbols: (); part number: RES_SM-34.8K,E020912,1/10W,1,R0402; tolerance: 1
RFILT = RES: User Part Number: UPN; alternate symbols: (); part number: RES_SM-1,E015181,1/10W,1,R0603
RFREQ = RES: Tolerance: 1; User Part Number: UPN; alternate symbols: (); part number: RES_SM-88.7K,E020516,1/10W,1,R0402; tolerance: 1
U1 = ICATSAM3UXXX: Tolerance: N/A; User Part Number: UPN; alternate symbols: (); part number: ICATSAM3UXXX_SM-ATSAM3U2CA-AU,E021585,LQFP100; tolerance: N/A
U2 = ADM1178: Tolerance: N/A; User Part Number: UPN; alternate symbols: (); part number: ADM1178_SM-ADM1178-1ARMZ,E016603,RM10; tolerance: N/A
U3 = ADP7118: User Part Number: UPN; Tolerance: N/A; alternate symbols: (); part number: ADP7118_SM-ADP7118ACPZN3.3,E023531,DFN6_2X2_PAD1_6X1; tolerance: N/A
U4 = ADR38X: User Part Number: UPN; Tolerance: N/A; alternate symbols: (); part number: ADR38X_SM-ADR381ARTZ,E012776,SOT23; tolerance: N/A
U5 = ADP2442: User Part Number: UPN; Tolerance: N/A; alternate symbols: (); part number: ADP2442_SM-ADP2442ACPZ,E018413,QFN12_3X3_PAD1_6X1_6; tolerance: N/A
U6 = ADM7171: Tolerance: N/A; User Part Number: UPN; alternate symbols: (); part number: ADM7171_SM-ADM7171ACPZ,E021119,DFN8_3X3_PAD2_38X1_64; tolerance: N/A
U7 = ADP7118: User Part Number: UPN; Tolerance: N/A; alternate symbols: (); part number: ADP7118_SM-ADP7118ACPZN5.0,E021288,DFN6_2X2_PAD1_6X1; tolerance: N/A
U9 = ADP1614: User Part Number: UPN; Tolerance: N/A; alternate symbols: (); part number: ADP1614_SM-ADP1614ACPZ-1.3,E019029,QFN10_3X3_PAD2_38X1_64; tolerance: N/A
U10 = AD56X3: Tolerance: N/A; User Part Number: UPN; alternate symbols: (); part number: AD56X3_SM-AD5663RBRMZ-5,E026980,RM10; tolerance: N/A
U11 U12 = AD7682: User Part Number: UPN; Tolerance: N/A; alternate symbols: (); part number: AD7682_SM-AD7682BCPZ,E007770,QFN20_4X4_PAD2_5X2_5; tolerance: N/A
UA9 UB9 = AD51X2A: User Part Number: UPN; Tolerance: N/A; alternate symbols: (); part number: AD51X2A_SM-AD5122ABCPZ10,E020276,QFN16_3X3_PAD1_6X1_6; tolerance: N/A
UA11 UB11 = ADG161X_V2: Tolerance: N/A; User Part Number: UPN; alternate symbols: (); part number: ADG161X_V2_SM-ADG1611BCPZ,E018673,QFN16_4X4_PAD2_5X2_5; tolerance: N/A
UA12 UB12 = AD8210: Tolerance: N/A; User Part Number: UPN; alternate symbols: (); part number: AD8210_SM-AD8210WYRZ,E012674,SO8; tolerance: N/A
Y1 = XTAL: Tolerance: 30PPM; User Part Number: UPN; alternate symbols: (); part number: XTAL_SM-12MEGHZ,E021373,YSML197W126H59; tolerance: 30PPM

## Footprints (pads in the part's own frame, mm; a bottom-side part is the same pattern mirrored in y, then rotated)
C0402
  rect 0.889x0.813 smd: 1(-0.635,0) 2(0.635,0)
C0402#2
  rect 0.483x0.559 smd: 1(-0.438,0) 2(0.438,0)
C0402#3
  rect 0.61x0.61 smd: 1(-0.495,0) 2(0.495,0)
C0603
  rect 1.092x1.194 smd: 1(-0.851,0) 2(0.851,0)
C0603#2
  rect 0.762x0.889 smd: 1(-0.699,0) 2(0.699,0)
C0603#3
  rect 0.483x0.559 smd: 1(-0.438,0) 2(0.438,0)
C0805
  rect 1.295x1.6 smd: 1(-0.953,0) 2(0.953,0)
C0805#2
  rect 0.94x1.346 smd: 1(-0.8,0) 2(0.8,0)
C1210-2
  rect 1.575x2.692 smd: 1(-1.397,0) 2(1.397,0)
C3528
  rect 2.032x2.21 smd: N(1.524,0) P(-1.524,0)
CNFCI10103592-0001LF
  rect 0.406x1.753 smd: 1(-1.3,-2.709) 2(-0.65,-2.709) 3(0,-2.709) 4(0.65,-2.709) 5(1.3,-2.709)
  custom 0.667x0.667 hole 0.711x1.295: 6(-4.1,0.165) 7(4.1,0.165)
  rect 2.007x1.448 hole 1.041x0.66: 8(-2.425,-2.915) 9(2.425,-2.915)
CNHDR2X5H245
  rect 0.737x2.794 smd: 1(-2.54,-2.032) 2(-2.54,2.032) 3(-1.27,-2.032) 4(-1.27,2.032) 5(0,-2.032) 6(0,2.032) 7(1.27,-2.032) 8(1.27,2.032) 9(2.54,-2.032) 10(2.54,2.032)
CNHDRRA1X6H108
  rect 1.524x1.524 hole 1.016: 1(0,0)
  round 1.524 hole 1.016: 2(2.54,0) 3(5.08,0) 4(7.62,0) 5(10.16,0) 6(12.7,0)
CNHDRRA1X8H108
  rect 1.524x1.524 hole 1.016: 1(0,0)
  round 1.524 hole 1.016: 2(2.54,0) 3(5.08,0) 4(7.62,0) 5(10.16,0) 6(12.7,0) 7(15.24,0) 8(17.78,0)
D0402
  rect 0.61x0.508 smd: 1(-0.56,0) 2(0.56,0)
DFN6_2X2_PAD1_6X1
  oval 0.305x0.864 smd: 1(-0.65,-1.082) 2(0,-1.082) 3(0.65,-1.082) 4(0.65,1.082) 5(0,1.082) 6(-0.65,1.082)
  rect 1.6x0.991 smd: PAD(0,0)
DFN8_3X3_PAD2_38X1_64
  oval 0.305x0.838 smd: 1(-0.75,-1.45) 2(-0.25,-1.45) 3(0.25,-1.45) 4(0.75,-1.45) 5(0.75,1.45) 6(0.25,1.45) 7(-0.25,1.45) 8(-0.75,1.45)
  rect 2.388x1.651 smd: PAD(0,0)
DIO214AA
  rect 1.27x2.108 smd: A(1.981,0) C(-1.981,0)
JPSLD02
  rect 0.61x1.549 smd: 1(-0.406,0) 2(0.406,0)
L0603
  rect 0.889x0.813 smd: 1(-0.737,0) 2(0.737,0)
L0805
  rect 1.143x1.27 smd: 1(-0.953,0) 2(0.953,0)
L9075
  rect 1.016x1.778 smd: 1(-0.889,0) 2(0.889,0)
LED1206H11
  rect 1.499x1.6 smd: A(1.799,0) C(-1.799,0)
LQFP100
  rect 0.254x1.524 smd: 1(-6,-7.75) 2(-5.5,-7.75) 3(-5,-7.75) 4(-4.5,-7.75) 5(-4,-7.75) 6(-3.5,-7.75) 7(-3,-7.75) 8(-2.5,-7.75) 9(-2,-7.75) 10(-1.5,-7.75) 11(-1,-7.75) 12(-0.5,-7.75) 13(0,-7.75) 14(0.5,-7.75) 15(1,-7.75) 16(1.5,-7.75) 17(2,-7.75) 18(2.5,-7.75) 19(3,-7.75) 20(3.5,-7.75) 21(4,-7.75) 22(4.5,-7.75) 23(5,-7.75) 24(5.5,-7.75) 25(6,-7.75) 51(6,7.75) 52(5.5,7.75) 53(5,7.75) 54(4.5,7.75) 55(4,7.75) 56(3.5,7.75) 57(3,7.75) 58(2.5,7.75) 59(2,7.75) 60(1.5,7.75) 61(1,7.75) 62(0.5,7.75) 63(0,7.75) 64(-0.5,7.75) 65(-1,7.75) 66(-1.5,7.75) 67(-2,7.75) 68(-2.5,7.75) 69(-3,7.75) 70(-3.5,7.75) 71(-4,7.75) 72(-4.5,7.75) 73(-5,7.75) 74(-5.5,7.75) 75(-6,7.75)
  rect 1.524x0.254 smd: 26(7.75,-6) 27(7.75,-5.5) 28(7.75,-5) 29(7.75,-4.5) 30(7.75,-4) 31(7.75,-3.5) 32(7.75,-3) 33(7.75,-2.5) 34(7.75,-2) 35(7.75,-1.5) 36(7.75,-1) 37(7.75,-0.5) 38(7.75,0) 39(7.75,0.5) 40(7.75,1) 41(7.75,1.5) 42(7.75,2) 43(7.75,2.5) 44(7.75,3) 45(7.75,3.5) 46(7.75,4) 47(7.75,4.5) 48(7.75,5) 49(7.75,5.5) 50(7.75,6) 76(-7.75,6) 77(-7.75,5.5) 78(-7.75,5) 79(-7.75,4.5) 80(-7.75,4) 81(-7.75,3.5) 82(-7.75,3) 83(-7.75,2.5) 84(-7.75,2) 85(-7.75,1.5) 86(-7.75,1) 87(-7.75,0.5) 88(-7.75,0) 89(-7.75,-0.5) 90(-7.75,-1) 91(-7.75,-1.5) 92(-7.75,-2) 93(-7.75,-2.5) 94(-7.75,-3) 95(-7.75,-3.5) 96(-7.75,-4) 97(-7.75,-4.5) 98(-7.75,-5) 99(-7.75,-5.5) 100(-7.75,-6)
LSML126W90H59
  rect 0.889x2.54 smd: 1(-1.372,0) 2(1.372,0)
LSMSQ157H122
  rect 0.965x3.708 smd: 1(-1.181,0) 2(1.181,0)
MSOP8
  rect 0.305x1.321 smd: 1(-0.975,-2.3) 2(-0.325,-2.3) 3(0.325,-2.3) 4(0.975,-2.3) 5(0.975,2.3) 6(0.325,2.3) 7(-0.325,2.3) 8(-0.975,2.3)
POWERDI323
  rect 0.864x0.737 smd: A(1.09,0)
  rect 1.753x1.016 smd: C(-0.65,0)
QFN10_3X3_PAD2_38X1_64
  oval 0.254x0.813 smd: 1(-1,-1.5) 2(-0.5,-1.5) 3(0,-1.5) 4(0.5,-1.5) 5(1,-1.5) 6(1,1.5) 7(0.5,1.5) 8(0,1.5) 9(-0.5,1.5) 10(-1,1.5)
  rect 2.388x1.651 smd: PAD(0,0)
QFN12_3X3_PAD1_6X1_6
  oval 0.305x0.991 smd: 1(-0.5,-1.57) 2(0,-1.57) 3(0.5,-1.57) 7(0.5,1.57) 8(0,1.57) 9(-0.5,1.57)
  oval 0.991x0.305 smd: 4(1.57,-0.5) 5(1.57,0) 6(1.57,0.5) 10(-1.57,0.5) 11(-1.57,0) 12(-1.57,-0.5)
  rect 1.6x1.6 smd: PAD(0,0)
QFN16_3X3_PAD1_6X1_6
  oval 0.305x0.889 smd: 1(-0.75,-1.5) 2(-0.25,-1.5) 3(0.25,-1.5) 4(0.75,-1.5) 9(0.75,1.5) 10(0.25,1.5) 11(-0.25,1.5) 12(-0.75,1.5)
  oval 0.889x0.305 smd: 5(1.5,-0.75) 6(1.5,-0.25) 7(1.5,0.25) 8(1.5,0.75) 13(-1.5,0.75) 14(-1.5,0.25) 15(-1.5,-0.25) 16(-1.5,-0.75)
  rect 1.6x1.6 smd: PAD(0,0)
QFN16_4X4_PAD2_5X2_5
  oval 0.356x0.991 smd: 1(-0.975,-1.974) 2(-0.325,-1.974) 3(0.325,-1.974) 4(0.975,-1.974) 9(0.975,1.974) 10(0.325,1.974) 11(-0.325,1.974) 12(-0.975,1.974)
  oval 0.991x0.356 smd: 5(1.974,-0.975) 6(1.974,-0.325) 7(1.974,0.325) 8(1.974,0.975) 13(-1.974,0.975) 14(-1.974,0.325) 15(-1.974,-0.325) 16(-1.974,-0.975)
  rect 2.489x2.489 smd: PAD(0,0)
QFN20_4X4_PAD2_5X2_5
  oval 0.305x1.041 smd: 1(-1,-1.97) 2(-0.5,-1.97) 3(0,-1.97) 4(0.5,-1.97) 5(1,-1.97) 11(1,1.97) 12(0.5,1.97) 13(0,1.97) 14(-0.5,1.97) 15(-1,1.97)
  oval 1.041x0.305 smd: 6(1.97,-1) 7(1.97,-0.5) 8(1.97,0) 9(1.97,0.5) 10(1.97,1) 16(-1.97,1) 17(-1.97,0.5) 18(-1.97,0) 19(-1.97,-0.5) 20(-1.97,-1)
  rect 2.489x2.489 smd: PAD(0,0)
R0402
  rect 0.483x0.508 smd: 1(-0.43,0) 2(0.43,0)
R0402#2
  rect 0.889x0.813 smd: 1(-0.635,0) 2(0.635,0)
R0402#3
  rect 0.533x0.635 smd: 1(-0.45,0) 2(0.45,0)
R0603
  rect 1.092x1.194 smd: 1(-0.851,0) 2(0.851,0)
R0603#2
  rect 0.762x0.889 smd: 1(-0.699,0) 2(0.699,0)
R0603#3
  rect 0.61x0.889 smd: 1(-0.75,0) 2(0.75,0)
R0805
  rect 1.295x1.397 smd: 1(-0.953,0) 2(0.953,0)
R1206
  rect 1.6x1.6 smd: 1(-1.397,0) 2(1.397,0)
RM10
  rect 0.305x1.321 smd: 1(-1,-2.171) 2(-0.5,-2.171) 3(0,-2.171) 4(0.5,-2.171) 5(1,-2.171) 6(1,2.171) 7(0.5,2.171) 8(0,2.171) 9(-0.5,2.171) 10(-1,2.171)
SO8
  rect 0.61x2.184 smd: 1(-1.905,-2.54) 2(-0.635,-2.54) 3(0.635,-2.54) 4(1.905,-2.54) 5(1.905,2.54) 6(0.635,2.54) 7(-0.635,2.54) 8(-1.905,2.54)
SOT23
  rect 1.016x1.397 smd: 1(-0.94,-1.118) 2(0.94,-1.118) 3(0,1.118)
SOT23_6
  rect 0.711x1.27 smd: 1(-0.953,-1.27) 2(0,-1.27) 3(0.953,-1.27) 4(0.953,1.27) 5(0,1.27) 6(-0.953,1.27)
SOT363H43
  rect 0.432x0.61 smd: 1(-0.65,-0.95) 2(0,-0.95) 3(0.65,-0.95) 4(0.65,0.95) 5(0,0.95) 6(-0.65,0.95)
TSOP6
  rect 0.508x1.346 smd: 1(-1.003,-1.257) 2(0,-1.257) 3(1.003,-1.257) 4(1.003,1.257) 5(0,1.257) 6(-1.003,1.257)
unnamed#2
  round 1.016 smd: (0,0)
YSML197W126H59
  rect 2.007x2.388 smd: 1(-2.003,0) 2(2.003,0)

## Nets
1V8: C3.1 C4.2(N2) C24.2(N2) C33.2(N2) C35.2(N2) C37.2(N2) C50.2(N2) C52.2(N2) U1.9 U1.34 U1.52 U1.59 U1.73 U1.83 U1.87
2V5: A4.5 C40.2(N2) C44.2(N2) C49.2(N2) C71.2(N2) E2.2(N2) R9.1 R17.1 R24.1 UA12.3 UA12.7 UB12.3 UB12.7
3V3: C1.1 C2.2(N2) C19.2(N2) C21.2(N2) C32.2(N2) C34.2(N2) C36.2(N2) C38.2(N2) C48.2(N2) C51.2(N2) C53.2(N2) C56.2(N2) C66.2(N2) D5.2 D5.5(C2) D6.2 D6.5(C2) DS1.A(P) DS2.A(P) DS3.A(P) E3.2(N2) JTAG.1 P3.6(N6) R1.1 R2.1 R13.1 R56.1 R93.1 U1.1 U1.22 U1.36 U1.45 U1.53 U1.60 U1.79 U1.88 U11.15(VIO) U12.15(VIO) UA9.10 UA9.16 UB9.10 UB9.13 UB9.16
4V5: C17.1 C18.2(N2) Q1.4(S) R37.2(N2) R54.1
4V5_U5: CC.2(N2) CIN1.1 R37.1 U5.3 U5.9(VIN)
5V0: A2.2(VDD) B2.2(VDD) B4.5 C13.2(N2) C22.1 C25.2(N2) C31.1 C55.1 C59.1 C61.2(N2) C63.2(N2) C64.2(N2) C65.1 C69.1 C70.1 C108.1 D2.2 D2.5(C2) D11.2 D11.5(C2) U4.1 U7.1(VOUT) U7.2 U10.9 U11.1 U11.20 U12.1 U12.20 UA9.9 UA12.6(V_POS) UB9.9 UB12.6(V_POS)
6V0: A3.8 A4.8 B3.8 B4.8 C41.2(N2) C46.2(N2) C47.1 C54.2(N2) C58.2(N2) C62.1 C68.1 C76.1 C77.2(N2) C78.1 C79.2(N2) C80.1 C81.2(N2) C82.1 C106.1 D3.A(P) D7.2 D7.5(C2) D10.2 D10.5(C2) R97.1 U6.1 U6.2(VOUT2) U8.8 UA11.11 UB11.11
6V5: C29.1 C45.1 E4.1 L4.2(N2) R18.1
-1V0: A3.4(V-) A4.4(VS-) B3.4(V-) B4.4(VS-) C41.1 C47.2(N2) C54.1 C76.2(N2) C77.1 C78.2(N2) C79.1 C80.2(N2) C81.1 C82.2(N2) C90.2(N2) C91.1 C92.2(N2) C93.1 D7.1 D7.4 D10.1 D10.4 R36.1 U8.4(V-) UA11.2(VSS) UA11.PAD UB11.2(VSS) UB11.PAD
-1V0_U5: CC2.1 COUT2.N(N2) CSS.1 CVCC.2(N2) D1.A(P) L2.1 R36.2(N2) RC1.1 RF2.1 RFILT.1 RFREQ.1 U5.12 U5.PAD
GND: A2.3 B2.3 C1.2(N2) C2.1 C3.2(N2) C4.1 C5.1 C6.2(N2) C7.2(N2) C8.1 C9.1 C10.2(N2) C11.1 C12.2(N2) C13.1 C14.1 C15.2(N2) C17.2(N2) C18.1 C19.1 C20.2(N2) C21.1 C22.2(N2) C23.2(N2) C24.1 C25.1 C26.1 C27.2(N2) C28.2(N2) C29.2(N2) C30.2(N2) C31.2(N2) C32.1 C33.1 C34.1 C35.1 C36.1 C37.1 C38.1 C40.1 C42.1 C44.1 C45.2(N2) C46.1 C48.1 C49.1 C50.1 C51.1 C52.1 C53.1 C55.2(N2) C56.1 C58.1 C59.2(N2) C61.1 C62.2(N2) C63.1 C64.1 C65.2(N2) C66.1 C68.2(N2) C69.2(N2) C70.2(N2) C71.1 C72.1 C73.1 C74.1 C75.1 C90.1 C91.2(N2) C92.1 C93.2(N2) C94.1 C95.1 C96.2(N2) C97.2(N2) C99.1 C101.1 C104.2(N2) C105.1 C106.2(N2) C107.2(N2) C108.2(N2) C109.1 C112.1 CIN1.2(N2) COUT1.1 COUT2.P D1.C D2.1 D2.4 D5.1 D5.4 D6.1 D6.4 D8.1 D9.1 D11.1 D11.4 JTAG.3 JTAG.5 JTAG.9 L1.2(N2) P1.4 P1.5(N5) P2.4 P2.5 P3.5 P4.2(N2) P5.2(N2) P6.2(N2) R3.1 R8.2(N2) R12.2(N2) R17.2(N2) R19.1 R22.2(N2) R27.2(N2) R38.2(N2) R40.2(N2) R55.1 R62.2(N2) R95.1 R98.2(N2) RF1.2(N2) U1.3 U1.35 U1.46 U1.61 U1.72 U1.82 U1.89 U2.4 U2.8 U3.3 U3.PAD U4.3 U6.6 U6.PAD U7.3 U7.PAD U9.4 U9.5 U9.PAD U10.3 U11.4 U11.5 U11.6 U11.8 U11.10 U11.17 U11.19 U11.PAD U12.4 U12.5 U12.6 U12.8 U12.10 U12.17 U12.19 U12.PAD UA9.1 UA9.5 UA9.13 UA9.14 UA9.PAD UA11.3 UA11.13 UA12.2 UB9.1 UB9.5 UB9.14 UB9.PAD UB11.3 UB11.13 UB12.2
VCC: CVCC.1 CVCC2.1 R21.2(N2) U5.11
CHA: A2.4 D7.6 P2.2 R28.2(N2) R48.2(N2) R70.1 UA11.4 UA11.9
CHA_2V5: C102.2(N2) P2.3 R39.2(N2) R49.2(N2) R57.2(N2) UA11.16 UB11.16
CHA_IN: D7.3 P2.1 R29.2(N2) R71.1
CHB: B2.4 D10.6 P2.7 R63.2(N2) R64.2(N2) R67.1 UB11.4 UB11.9
CHB_5V: C57.2(N2) P2.6 R33.2(N2) R65.2(N2) R66.2(N2)
CHB_IN: D10.3 P2.8(N8) R31.2(N2) R68.1
CLR_N: U1.12 U10.5
CNV1: U1.86 U11.11 U12.11
D+: D9.2(N2) P1.3 R4.2(N2) U1.76
D+_A: R4.1 U1.81
D-: D8.2(N2) P1.2 R5.2(N2) U1.77
D-_A: R5.1 U1.80
FB: R18.2(N2) R19.2(N2) U9.2
ISENSE-A: C27.1 R15.2(N2) R22.1 U8.3 UA9.2 UA9.3
ISENSE-A_BUF: R86.1 R92.1 U8.1 U8.2
ISENSE-B: C28.1 R16.2(N2) R40.1 U8.5 UB9.2 UB9.3
ISENSE-B_BUF: R88.1 R90.1 U8.6 U8.7
LDAC_N: U1.6 U10.4
NRST: JTAG.10(N5) U1.57
OVC_FAULT: R93.2(N2) U1.67 U2.10
PA0: D5.6 R41.2(N2) U1.26
PA1: D5.3 R42.2(N2) U1.27
PA2: D6.6 R43.2(N2) U1.28
PA3: D6.3 R53.2(N2) U1.29
PA4: R14.1 U1.30
PA5: R23.1 U1.31
PA6: R35.1 U1.32
PA7: R44.1 U1.33
PA28: R50.2(N2) U1.84
PA29: R52.2(N2) U1.85
PB15: R51.2(N2) U1.16
PWR_ENABLE: U1.68 U2.3
RX1: R80.2(N2) U1.20
RX2: R83.2(N2) U1.21
SCK: R79.2(N2) U11.13
SCK0: R72.1 U1.14
SCK1: R79.1 U1.23
SCK2: R82.1 U1.24
SCL: R2.2(N2) U1.39 U2.6 UA9.11 UB9.11
SDA: R1.2(N2) U1.38 U2.7 UA9.12 UB9.12
SWMODE-A: A2.1 U1.66
SWMODE-B: B2.1 U1.65
SYNC_N: U1.13 U10.6
TCK: JTAG.4 U1.56
TDI: JTAG.8 U1.51
TDO: JTAG.6 U1.54
TMS: JTAG.2 U1.55
TX0: R73.1 U1.17
TX1: R78.1 U1.19
TX2: R81.1 U1.5
UA11-IN0: U1.90 UA11.15
UA11-IN1: U1.91 UA11.14
UA11-IN2: U1.92 UA11.7
UA11-IN3: U1.7 UA11.6
UB11-IN0: U1.97 UB11.15
UB11-IN1: U1.98 UB11.14
UB11-IN2: U1.99 UB11.7
UB11-IN3: U1.100 UB11.6
UNNAMED_2_ADM1178_I544_GATE: Q1.3 U2.9
UNNAMED_2_ADM1178_I544_SENSE: Q1.1 Q1.2 Q1.5 Q1.6 R6.2(N2) U2.2
UNNAMED_2_ADM1178_I544_TIMER: C11.2(N2) U2.5
UNNAMED_2_ADM7171_I450_EN: C104.1 E4.2(N2) U6.5 U6.7 U6.8
UNNAMED_2_ADM7171_I450_SENSE: R97.2(N2) R98.1 U6.3
UNNAMED_2_ADM7171_I450_SS: C105.2(N2) U6.4
UNNAMED_2_ADP1614_I395_CLRES: R11.1 R12.1 U9.9
UNNAMED_2_ADP1614_I395_COMP: C20.1 C110.2(N2) U9.1
UNNAMED_2_ADP1614_I395_SS: C109.2(N2) U9.10
UNNAMED_2_ADP1614_I395_SW1: D4.A(P) L3.2(N2) U9.6 U9.7
UNNAMED_2_ADP2442_I24_BST: CBST.1 U5.10
UNNAMED_2_ADP2442_I24_COMP: CC1.2(N2) CC2.2(N2) U5.2
UNNAMED_2_ADP2442_I24_FB: RF1.1 RF2.2(N2) U5.1
UNNAMED_2_ADP2442_I24_FREQ: RFREQ.2(N2) U5.5
UNNAMED_2_ADP2442_I24_PGND: CC.1 COUT1.2(N2) CVCC2.2(N2) L2.2(N2) RFILT.2(N2) U5.7
UNNAMED_2_ADP2442_I24_SW: CBST.2(N2) L1.1 U5.8
UNNAMED_2_ADP2442_I24_SYNC: CSS.2(N2) R21.1 U5.6
UNNAMED_2_ADP7118_I458_EN: C107.1 D3.C U7.4 U7.6
UNNAMED_2_ADP7118_I458_SS: C112.2(N2) U7.5
UNNAMED_2_ADP7118_I522_SENSE: C14.2(N2) C15.1 E3.1 U3.1(VOUT) U3.2
UNNAMED_2_ADR38X_I459_VOUT: C8.2(N2) C10.1 E2.1 U4.2(VOUT)
UNNAMED_2_CAP_I360_N1: CC1.1 RC1.2(N2)
UNNAMED_2_CAP_I384_N2: C5.2(N2) R3.2(N2) U1.78
UNNAMED_2_CAP_I419_N1: C30.1 D4.C L4.1
UNNAMED_2_CAP_I439_N1: C23.1 R11.2(N2) R45.1 U9.3 U9.8(VIN)
UNNAMED_2_CAP_I486_N1: C110.1 R95.2(N2)
UNNAMED_2_CAP_I529_N1: C6.1 U1.74 Y1.1
UNNAMED_2_CAP_I530_N1: C7.1 U1.75 Y1.2(N2)
UNNAMED_2_CN5P4PSHLD_I378_GND1: C101.2(N2) P1.6 P1.7 P1.8 P1.9 R55.2(N2)
UNNAMED_2_CN5P4PSHLD_I378_N1: E1.2(N2) P1.1
UNNAMED_2_CN6P_I299_N1: P3.1 R14.2(N2) R50.1
UNNAMED_2_CN6P_I299_N2: P3.2 R23.2(N2) R52.1
UNNAMED_2_CN6P_I299_N3: P3.3 R35.2(N2) R51.1
UNNAMED_2_CN6P_I299_N4: P3.4 R44.2(N2) R53.1
UNNAMED_2_DIOLED_I548_N: DS1.C R41.1
UNNAMED_2_DIOLED_I553_N: DS2.C R43.1
UNNAMED_2_DIOLED_I554_N: DS3.C R42.1
UNNAMED_2_ICATSAM3UXXX_I532_ERA: R56.2(N2) U1.43
UNNAMED_2_ICATSAM3UXXX_I532_P_1: P5.1 U1.63
UNNAMED_2_ICATSAM3UXXX_I532_P_2: P4.1 U1.62
UNNAMED_2_ICATSAM3UXXX_I532_PA1: R13.2(N2) U1.41
UNNAMED_2_ICATSAM3UXXX_I532_PB2: P6.1 U1.64
UNNAMED_2_RES_I435_N2: L3.1 R45.2(N2) R54.2(N2)
UNNAMED_3_AD51X2A_I23_B1: A2.6 UA9.4 UA9.6
UNNAMED_3_AD51X2A_I23_B2: C43.1 UA9.7(W2) UA9.8
UNNAMED_3_AD56X3_I308_DIN: R73.2(N2) U10.8
UNNAMED_3_AD56X3_I308_SCLK: R72.2(N2) U10.7
UNNAMED_3_AD56X3_I308_VOUTA: R74.1 U10.1
UNNAMED_3_AD56X3_I308_VOUTB: R75.1 U10.2
UNNAMED_3_AD56X3_I308_VREFIN: C99.2(N2) U10.10(VREFIN/VREFOUT)
UNNAMED_3_AD7682_I51_DIN: R78.2(N2) U11.12
UNNAMED_3_AD7682_I51_IN0: R69.2(N2) U11.16
UNNAMED_3_AD7682_I51_IN1: R89.2(N2) U11.18
UNNAMED_3_AD7682_I51_IN2: R86.2(N2) U11.7
UNNAMED_3_AD7682_I51_IN3: R90.2(N2) U11.9
UNNAMED_3_AD7682_I51_REF: C72.2(N2) U11.2
UNNAMED_3_AD7682_I51_REFIN: C74.2(N2) U11.3
UNNAMED_3_AD7682_I51_SDO: R80.1 U11.14
UNNAMED_3_AD7682_I136_DIN: R81.2(N2) U12.12
UNNAMED_3_AD7682_I136_IN0: R87.2(N2) U12.16
UNNAMED_3_AD7682_I136_IN1: R91.2(N2) U12.18
UNNAMED_3_AD7682_I136_IN2: R88.2(N2) U12.7
UNNAMED_3_AD7682_I136_IN3: R92.2(N2) U12.9
UNNAMED_3_AD7682_I136_REF: C73.2(N2) U12.2
UNNAMED_3_AD7682_I136_REFIN: C75.2(N2) U12.3
UNNAMED_3_AD7682_I136_SCK: R82.2(N2) U12.13
UNNAMED_3_AD7682_I136_SDO: R83.1 U12.14
UNNAMED_3_AD8018_I5_INV: A4.2 R24.2(N2) R25.1 R26.1
UNNAMED_3_AD8018_I5_NINV: A3.1 A4.3
UNNAMED_3_AD8018_I5_OUT: A4.1 R46.1 R47.1
UNNAMED_3_AD8018_I67_INV: A4.6 R39.1 R60.1
UNNAMED_3_AD8018_I67_OUT: A4.7 R49.1 R57.1
UNNAMED_3_AD8210_I21_INV: R30.2(N2) UA11.5 UA12.1
UNNAMED_3_AD8210_I21_NINV: R84.2(N2) UA12.8
UNNAMED_3_AD8210_I21_OUT: R15.1 UA12.5
UNNAMED_3_ADA46612V2_I229_: A3.6 A3.7 R20.2(N2)
UNNAMED_3_ADA46612V2_I231_: A2.5 A3.2
UNNAMED_3_ADG161XV2_I178_D3: A3.5 R29.1 R38.1 UA11.8
UNNAMED_3_ADG161XV2_I178_S1: R48.1 UA11.1
UNNAMED_3_ADG161XV2_I178_S2: R28.1 UA11.12
UNNAMED_3_CAP_I224_N1: C67.1 R26.2(N2)
UNNAMED_3_CAP_I224_N2: C43.2(N2) C67.2(N2) R25.2(N2) R30.1 R46.2(N2) R47.2(N2) R84.1
UNNAMED_3_CAP_I242_N2: C94.2(N2) R74.2(N2) R76.1
UNNAMED_3_CAP_I243_N2: C95.2(N2) R75.2(N2) R77.1
UNNAMED_3_CAP_I280_N1: C102.1 R60.2(N2)
UNNAMED_4_AD51X2A_I27_A2: B2.6 UB9.4 UB9.6
UNNAMED_4_AD51X2A_I27_B2: C39.1 UB9.7(W2) UB9.8
UNNAMED_4_AD8018_I52_INV: B4.6 R33.1 R58.1
UNNAMED_4_AD8018_I52_OUT: B4.7 R65.1 R66.1
UNNAMED_4_AD8018_I62_INV: B4.2 R9.2(N2) R10.1 R34.1
UNNAMED_4_AD8018_I62_NINV: B3.1 B4.3
UNNAMED_4_AD8018_I62_OUT: B4.1 R59.1 R61.1
UNNAMED_4_AD8210_I41_INV: R32.2(N2) UB11.5 UB12.1
UNNAMED_4_AD8210_I41_NINV: R85.2(N2) UB12.8
UNNAMED_4_AD8210_I41_OUT: R16.1 UB12.5
UNNAMED_4_ADA46612V2_I136_: B2.5 B3.2
UNNAMED_4_ADA46612V2_I138_: B3.6 B3.7 R7.2(N2)
UNNAMED_4_ADG161XV2_I97_D3: B3.5 R8.1 R31.1 UB11.8
UNNAMED_4_ADG161XV2_I97_S1: R64.1 UB11.1
UNNAMED_4_ADG161XV2_I97_S2: R63.1 UB11.12
UNNAMED_4_CAP_I135_N1: C84.1 R34.2(N2)
UNNAMED_4_CAP_I135_N2: C39.2(N2) C84.2(N2) R10.2(N2) R32.1 R59.2(N2) R61.2(N2) R85.1
UNNAMED_4_CAP_I157_N1: C57.1 R58.2(N2)
UNNAMED_4_DIO6PV2_I110_AC1: D2.6 R70.2(N2)
UNNAMED_4_DIO6PV2_I110_AC2: D2.3 R71.2(N2)
UNNAMED_4_DIO6PV2_I179_AC1: D11.6 R67.2(N2)
UNNAMED_4_DIO6PV2_I179_AC2: D11.3 R68.2(N2)
VSENSE-A: C42.2(N2) R20.1 R62.1 R69.1 R91.1
VSENSE-B: C26.2(N2) R7.1 R27.1 R87.1 R89.1
VSETPOINT-A: A3.3 C96.1 R76.2(N2)
VSETPOINT-B: B3.3 C97.1 R77.2(N2)
VUSB: C9.2(N2) C12.1 E1.1 R6.1 U2.1(VCC) U3.4 U3.6

Pads without a net: JTAG 7; U1 2 4 8 10 11 15 18 25 37 40 42 44 47 48 49 50 58 69 70 71 93 94 95 96; U3 5; U5 4; UA9 15; UA11 10; UA12 4; UB9 15; UB11 10; UB12 4

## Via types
v1: diameter 0.508, hole 0.254, TOP to BOTTOM, 461 vias

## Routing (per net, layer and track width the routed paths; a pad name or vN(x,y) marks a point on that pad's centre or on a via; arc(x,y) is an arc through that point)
1V8: length 25.4
  TOP w0.254: U1.59 14.35,22.4 C35.2 ; C4.2 10.35,3.73 U1.9 ; U1.34 21.27,10.96 22.2,10.04 22.51,10.04 22.64,9.91 ; U1.52 17.85,21.89 17.94,21.98 ; U1.83 3.68,15.46 v1(3.08,14.87) ; 7.65,22.11 7.35,21.8 U1.73 ; v1(3.08,13.47) U1.87
  TOP w0.305: C37.2 9.05,22.49 v1(8.67,22.11) 7.65,22.11 ; v1(3.08,13.47) 2.7,13.09 2.7,12.74 2.04,12.07 C52.2 ; v1(10.45,2.89) C4.2 ; 19.08,22.77 C33.2 ; C33.2 18.5,23.32 ; C33.2 19.67,23.32 ; C50.2 v1(3.08,14.87)
  TOP w0.381: 17.94,21.98 18.45,22.49 18.58,22.49
  TOP w0.406: C35.2 14.65,22.55 v1(15.27,22.55)
  TOP w0.508: 21.24,22.69 C3.1 20.26,23.46 ; v1(22.26,10.93) 22.64,10.55 22.64,9.91 22.77,9.79
  vias: v1(19.34,22.49) v1(19.97,23.12)
2V5: length 28.3
  TOP w0.305: UA12.3 57.95,41.54 56.68,40.27 UA12.7
  TOP w0.406: v1(52.92,39.5) C49.2 UA12.7
  TOP w0.508: UB12.7 55.03,6.36 C71.2 53.76,5.09 v1(52.99,5.09) ; C44.2 R24.1 ; R9.1 59.98,14.36 60.36,14.74 C40.2 60.87,14.61 60.87,11.88 v1(59.03,10.04) ; UB12.3 v1(59.85,7.63)
  TOP w0.635: v1(64.3,26.8) 64.3,26.3 64.68,25.92 R17.1 65.44,26.61 66.07,27.25 A4.5 ; v1(60.99,26.8) C44.2
  vias: v1(60.49,47.63) v1(60.49,46.87) v1(61.25,46.87) v1(67.92,52.71) v1(67.92,51.95) v1(68.68,52.71) v1(68.68,51.95)
3V3: length 60.6
  TOP w0.254: v1(26.05,12.39) R1.1 ; C19.2 16.85,3.64 U1.22 ; U1.88 3.72,12.96 3.08,12.33 v1(3.08,11.31) ; 22.33,16.46 U1.45 ; C48.2 13.85,22.33 U1.60 ; 22.77,11.95 22.66,11.96 U1.36 ; R2.1 v1(27.83,12.39) ; C2.2 6.36,3.66 6.36,3.94 6.35,3.95 U1.1
  TOP w0.305: UB9.10 49.7,5.22 v1(49.56,5.09) ; R93.1 v1(17.18,36.58) ; U11.15 28.5,26.79 27.85,27.44 v1(27.34,27.44) 26.58,28.2 C38.2 ; D5.5 D5.2 v1(25.82,4.45) ; v1(52.36,8.9) 51.71,8.25 UB9.16 ; C19.2 v1(16.87,2.86) ; v1(25.82,7.25) 25.56,7.5 D6.2 D6.5 ; U1.79 2.88,17.46 v1(2.45,17.03) 1.94,16.52 1.43,16.52 C51.2 ; C53.2 2.83,11.31 v1(3.08,11.31) ; UA9.16 v1(52.08,34.04) ; UA9.10 50.33,29.72 C66.2 ; v1(22.77,17.91) 23.21,17.47 C34.2 22.77,16.46 22.33,16.46 ; C21.2 37.75,27.88 v1(37.75,27.19) 38.01,27.19 38.28,26.92 U12.15 ; U1.53 v1(17.35,22.49) 17.05,22.49 16.92,22.62 C36.2 ; UB9.13 v1(51.45,6.1)
  TOP w0.406: C2.2 6.2,3.44 v1(5.69,3.44) ; C48.2 12.98,22.62 v1(12.86,22.74)
  TOP w0.508: C56.2 49.56,4.45 v1(49.56,5.09) ; C66.2 v1(51.98,29.09) ; v1(23.66,10.93) 23.33,10.93 23.02,11.23 23.02,11.69 22.77,11.95 ; C1.1 v1(2.83,7.82)
  TOP w0.635: DS2.A 9.45,2.91 v1(8.92,3.44) ; DS3.A 16.18,1.28 v1(17.31,1.28) ; DS1.A 3.08,1.38 v1(3.08,2.42)
  TOP w1.016: E3.2 -2.63,7.37
  BOTTOM w0.305: v1(34.32,3.82) 34.32,2.76 34.41,2.67
  BOTTOM w0.508: v1(14.51,31.25) 14.26,31.25 14,31 JTAG.1 ; v1(27.34,2.29) 28.42,2.29 R13.1
  vias: v1(-2.63,7.75) v1(-2.63,6.99) v1(-1.87,7.75) v1(-1.87,6.99)
4V5: length 13.6
  TOP w0.508: 19.33,45.82 Q1.4 ; Q1.4 18.35,46.37 ; Q1.4 20.3,46.37 ; R37.2 13.76,40.43 ; R37.2 11.96,40.43 ; R37.2 12.86,39.58
  TOP w0.762: C17.1 22.91,43.53 ; C17.1 21.1,43.53 ; C17.1 22.01,44.38 ; 22.13,45.17 R54.1 ; R54.1 21.23,46.02 ; R54.1 23.03,46.02 ; 18.49,43.63 C18.2 ; C18.2 19.59,44.58 ; C18.2 20.7,43.63
  vias: v1(12.23,39.38) v1(12.23,38.49) v1(13.5,39.38) v1(13.5,38.49) v1(19.97,44.84) v1(20.74,44.84) v1(21.5,44.71) v1(22.26,44.71)
4V5_U5: length 5.5
  TOP w0.305: U5.3 5.12,48.01 v1(4.86,48.27)
  TOP w0.508: 11.96,42.13 R37.1 ; R37.1 13.76,42.13 ; R37.1 12.86,42.98 ; CC.2 3.46,41.92 v1(4.48,42.93)
  vias: v1(6.89,43.44) v1(7.65,43.44) v1(8.42,43.44) v1(12.23,44.2) v1(12.23,43.19) v1(13.5,44.2) v1(13.5,43.19)
5V0: length 85.7
  TOP w0.254: U7.2 56.42,51.06
  TOP w0.305: UB9.9 49.19,5.61 48.68,5.09 v1(48.29,5.09) ; D11.2 D11.5 74.71,11.95 74.39,12.26 v1(73.31,12.26) ; U10.9 46.58,23.64 C63.2 ; U12.20 37.31,23.06 36.48,22.23 36.74,21.98 38.01,21.98 38.28,22.25 U12.1 ; C65.1 49.31,29.85 49.83,30.37 UA9.9 ; UB12.6 54.26,7.63 C70.1 53.88,8.01 v1(53.12,8.01) ; U11.20 27.1,23.52 26.7,23.12 26.7,22.36 27.09,21.98 28.23,21.98 28.5,22.25 U11.1 ; v1(43.6,18.8) B2.2 ; 55.6,49.95 U7.1 ; U7.1 U7.2 ; U7.1 56.34,50.41 ; 52.36,44.84 v1(52.36,43.7)
  TOP w0.381: D2.5 D2.2 ; 26.7,22.36 C61.2 24.25,22.36 C59.1 24.67,21.51 v1(24.67,20.96) ; v1(35.85,19.18) 35.85,20.29 C22.1 35.47,20.67 C25.2 36.48,22.23
  TOP w0.406: UA12.6 53.5,41.54 53.31,41.35 C69.1 v1(52.92,42.08) ; v1(71.28,46.74) 74.94,46.74 75.35,46.34 D2.2 ; v1(44.23,21.85) 44.23,22.83 C64.2 45.27,23.57 C63.2
  TOP w0.508: 57.21,50.07 U4.1 58.02,49.07 ; C55.1 v1(48.29,5.09) ; C65.1 v1(48.42,29.09) ; 56.23,47.9 C108.1 ; C108.1 56.23,49.4 ; C108.1 56.92,48.65 ; B4.5 65.82,16.52 65.82,15.12 C31.1 65.69,14.74 v1(65.69,13.98) ; C13.2 58.27,48.72 ; C13.2 57.72,48.14 ; C13.2 58.27,47.56
  BOTTOM w0.381: v1(35.85,19.18) 34.07,20.96 v1(24.67,20.96)
  BOTTOM w0.762: v1(71.28,46.74) 68.87,49.16 57.31,49.16 57.06,48.9 57.06,48.52
  vias: v1(56.17,47.63) v1(56.93,47.63)
